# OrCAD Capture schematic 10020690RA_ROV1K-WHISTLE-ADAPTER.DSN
size B; title: ROV1k WHISTLE ADAPTER; note: 10020690
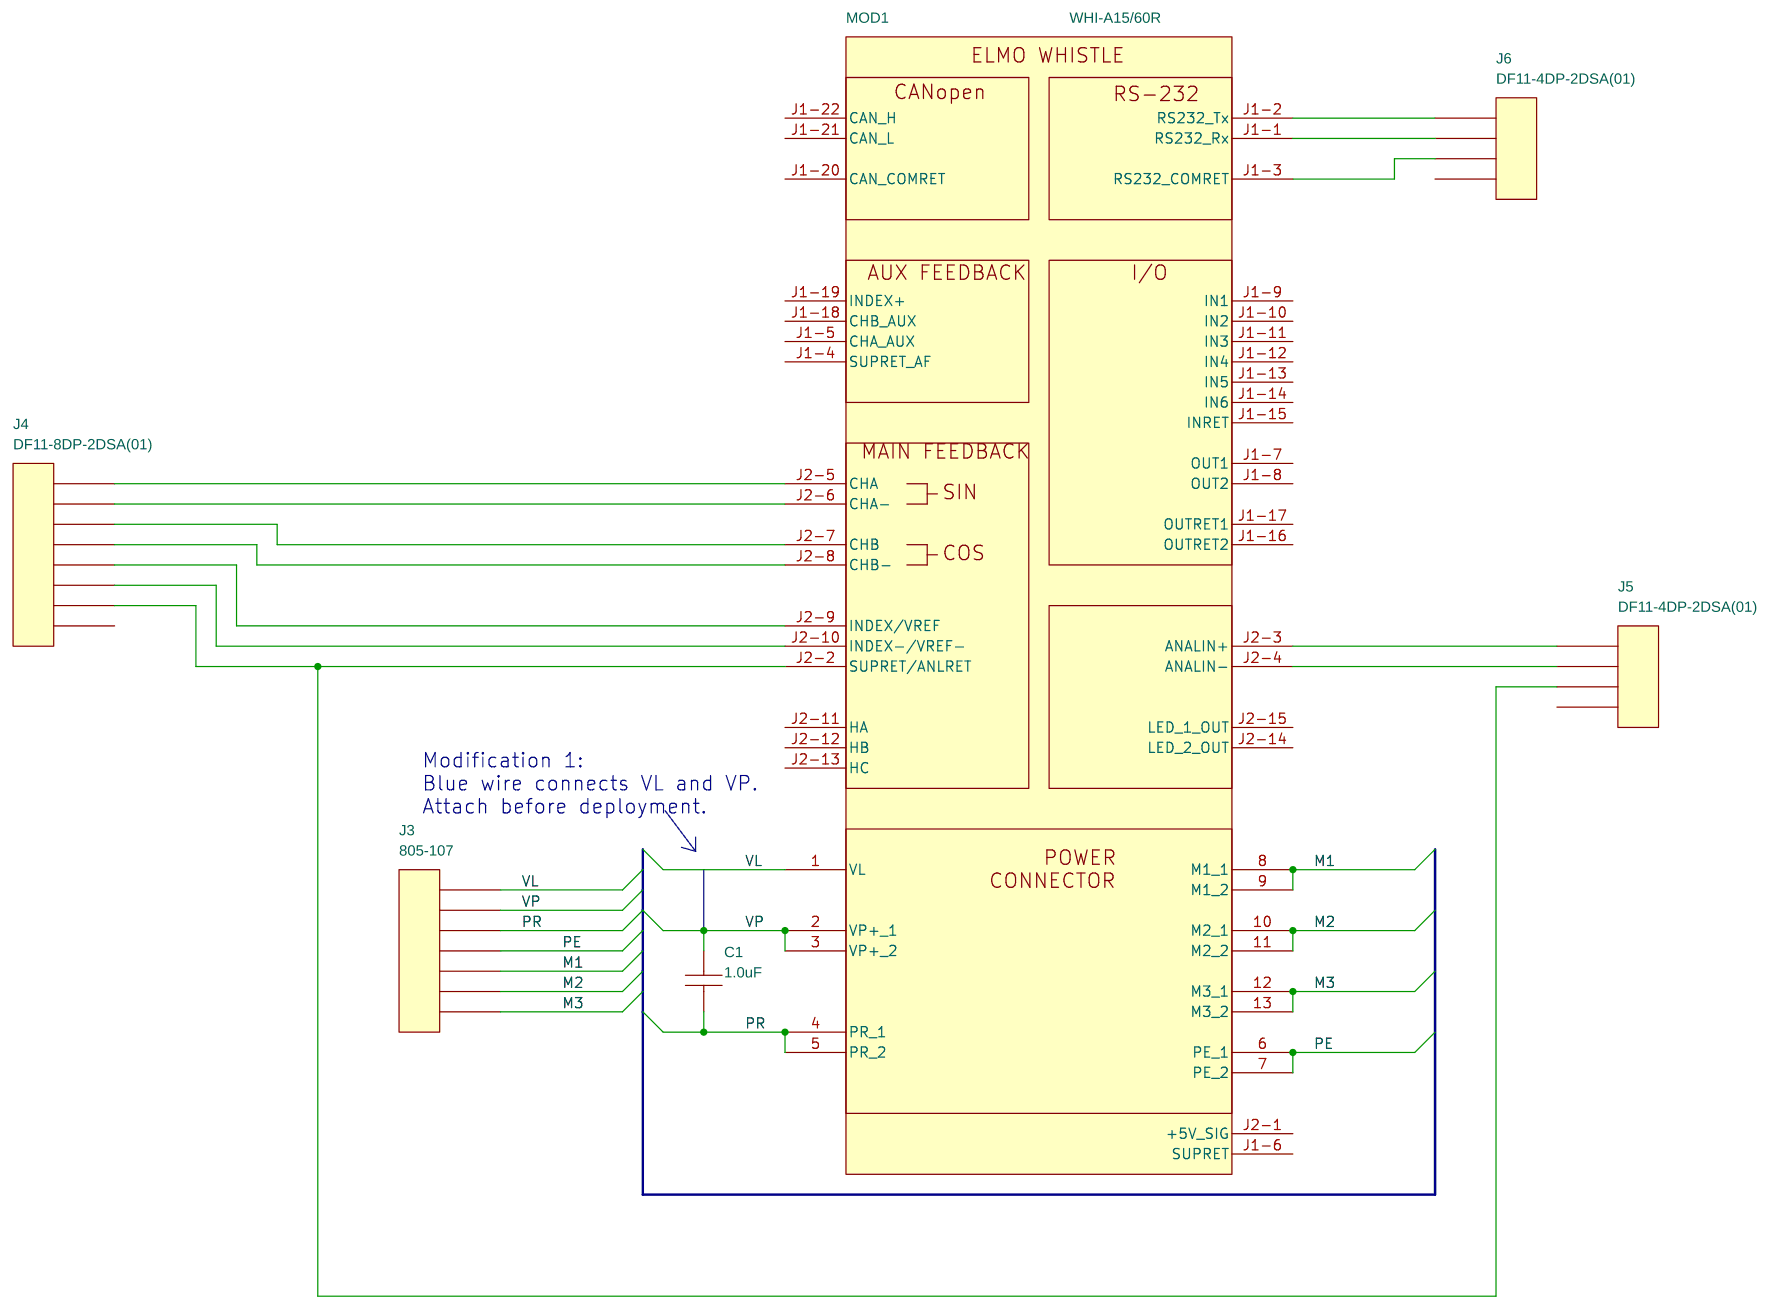
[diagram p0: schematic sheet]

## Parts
C1  1.0uF  [CAPC2012X145N]
J3  805-107  [WAGO_805-107]
J4  DF11-8DP-2DSA(01)  [HIROSE_DF11-8DP-2DSA]
J5  DF11-4DP-2DSA(01)  [HIROSE_DF11-4DP-2DSA]
J6  DF11-4DP-2DSA(01)  [HIROSE_DF11-4DP-2DSA]
MOD1  WHI-A15/60R  [ELMO_WHISTLE]

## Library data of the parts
C1 = CAP: CAP CER 1.0UF 100V X7S 0805; CLASS: DISCRETE; Dielectric Type: Capacitors; PART_NUMBER: C2012X7S2A105K; Package Size: 0805 (2012 Metric); TMP Manufacturer: TDK Corporation; TMP Manufacturer PN: C2012X7S2A105K; Temperature Coefficient: X7S; Tolerance: ±10%
J3 = CON7: WAGO - 805-107 - PCB TRM STRIP 2 PIN 7-P. 3.5MM GRAY; CLASS: IO; TMP Manufacturer: WAGO
J4 = CON8: CONN HEADER 8POS 2MM PCB GOLD; CLASS: IO; Package Size: 0.118" (3.00mm); TMP Manufacturer: Hirose Electric Co Ltd
J5 J6 = CON4: CONN HEADER 4POS 2MM PCB GOLD; CLASS: IO; Package Size: 0.118" (3.00mm); TMP Manufacturer: Hirose Electric Co Ltd
MOD1 = ELMO_WHI-Axx_yyyR: MOTOR CONTROLLER; CLASS: DISCRETE; PART_NUMBER: WHI-A15-60R; TMP Manufacturer: ELMO

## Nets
M1: J3.3 MOD1.8(M1_1) MOD1.9(M1_2)
M2: J3.2 MOD1.10(M2_1) MOD1.11(M2_2)
M3: J3.1 MOD1.12(M3_1) MOD1.13(M3_2)
PE: J3.4 MOD1.6(PE_1) MOD1.7(PE_2)
PR: C1.2 J3.5 MOD1.4(PR_1) MOD1.5(PR_2)
VL: J3.7 MOD1.1(VL)
VP: C1.1 J3.6 MOD1.2(VP+_1) MOD1.3(VP+_2)
N00583: J4.1 MOD1.J2-5(CHA)
N00587: J4.2 MOD1.J2-6(CHA-)
N00591: J4.3 MOD1.J2-7(CHB)
N00606: J4.4 MOD1.J2-8(CHB-)
N00618: J4.5 MOD1.J2-9(INDEX/VREF)
N00631: J4.6 MOD1.J2-10(INDEX-/VREF-)
N00643: J4.7 J5.3 MOD1.J2-2(SUPRET/ANLRET)
N01292: J6.1 MOD1.J1-2(RS232_Tx)
N01296: J6.2 MOD1.J1-1(RS232_Rx)
N01300: J6.3 MOD1.J1-3(RS232_COMRET)
N02903: J5.1 MOD1.J2-3(ANALIN+)
N02905: J5.2 MOD1.J2-4(ANALIN-)

Not connected (* = marked no-connect by the designer): J4 8; J5 4; J6 4; MOD1 J1-4(SUPRET_AF) J1-5(CHA_AUX) J1-6(SUPRET) J1-7(OUT1) J1-8(OUT2) J1-9(IN1) J1-10(IN2) J1-11(IN3) J1-12(IN4) J1-13(IN5) J1-14(IN6) J1-15(INRET) J1-16(OUTRET2) J1-17(OUTRET1) J1-18(CHB_AUX) J1-19(INDEX+) J1-20(CAN_COMRET) J1-21(CAN_L) J1-22(CAN_H) J2-1(+5V_SIG) J2-11(HA) J2-12(HB) J2-13(HC) J2-14(LED_2_OUT) J2-15(LED_1_OUT)

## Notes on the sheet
- Modification 1:
  Blue wire connects VL and VP.
  Attach before deployment.
